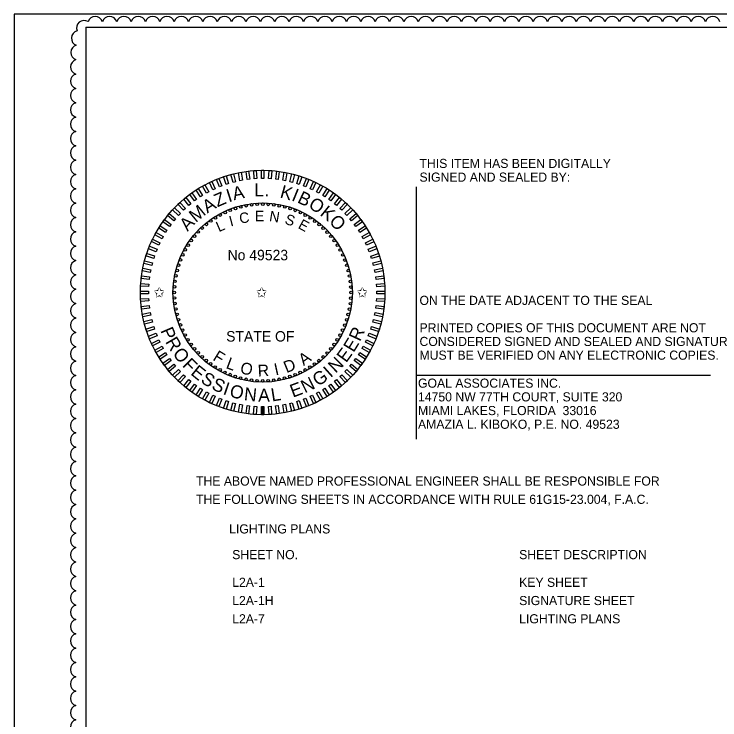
# Model space of a CAD drawing. Extents: x -811 to 10319, y -2309 to 9962.
# Drawn here: x -811.43 to -806.03, y -2291.82 to -2286.41 of the extents above; entities that cross this region are included whole.
import ezdxf

# ---------------------------------------------------------------- set-up
doc = ezdxf.new("R2010")
doc.units = 0
for name, color, linetype in [('AdhocPoint_dp', 7, 'Continuous'), ('PlotBorder_dp', 7, 'Continuous'), ('ScratchEle_dp', 7, 'Continuous'), ('TextMinor', 7, 'Continuous'), ('TextMisc', 7, 'Continuous'), ('TextNotes', 7, 'Continuous'), ('TextShtNo', 7, 'Continuous')]:
    doc.layers.add(name, color=color, linetype=linetype)

msp = doc.modelspace()

# ---------------------------------------------------------------- linework, layer by layer
at = {"layer": 'AdhocPoint_dp'}
for p, q in [((-808.3546, -2287.7325), (-808.3546, -2289.6672)), ((-808.3546, -2289.1772), (-806.0979, -2289.1772))]:
    msp.add_line(p, q, dxfattribs=at)
at = {"layer": 'PlotBorder_dp'}
msp.add_lwpolyline([(-811.435, -2297.0086), (-794.935, -2297.0086), (-794.935, -2286.4086), (-811.435, -2286.4086)], close=True, dxfattribs=at)
at = {"layer": 'ScratchEle_dp'}
for centre, start, end in [((-810.8137, -2286.4839), 17.5, 162.5), ((-810.7037, -2286.4839), 17.5, 162.5), ((-810.5936, -2286.4839), 17.5, 162.5), ((-810.4836, -2286.4839), 17.5, 162.5), ((-810.3736, -2286.4839), 17.5, 162.5), ((-810.2635, -2286.4839), 17.5, 162.5), ((-810.1535, -2286.4839), 17.5, 162.5), ((-810.0434, -2286.4839), 17.5, 162.5), ((-809.9334, -2286.4839), 17.5, 162.5), ((-809.8233, -2286.4839), 17.5, 162.5), ((-809.7133, -2286.4839), 17.5, 162.5), ((-809.6033, -2286.4839), 17.5, 162.5), ((-809.4932, -2286.4839), 17.5, 162.5), ((-809.3832, -2286.4839), 17.5, 162.5), ((-809.2731, -2286.4839), 17.5, 162.5), ((-809.1631, -2286.4839), 17.5, 162.5), ((-809.053, -2286.4839), 17.5, 162.5), ((-808.943, -2286.4839), 17.5, 162.5), ((-808.8329, -2286.4839), 17.5, 162.5), ((-808.7229, -2286.4839), 17.5, 162.5), ((-808.6129, -2286.4839), 17.5, 162.5), ((-808.5028, -2286.4839), 17.5, 162.5), ((-808.3928, -2286.4839), 17.5, 162.5), ((-808.2827, -2286.4839), 17.5, 162.5), ((-808.1727, -2286.4839), 17.5, 162.5), ((-808.0626, -2286.4839), 17.5, 162.5), ((-807.9526, -2286.4839), 17.5, 162.5), ((-807.8425, -2286.4839), 17.5, 162.5), ((-807.7325, -2286.4839), 17.5, 162.5), ((-807.6225, -2286.4839), 17.5, 162.5), ((-807.5124, -2286.4839), 17.5, 162.5), ((-807.4024, -2286.4839), 17.5, 162.5), ((-807.2923, -2286.4839), 17.5, 162.5), ((-807.1823, -2286.4839), 17.5, 162.5), ((-807.0722, -2286.4839), 17.5, 162.5), ((-806.9622, -2286.4839), 17.5, 162.5), ((-806.8522, -2286.4839), 17.5, 162.5), ((-806.7421, -2286.4839), 17.5, 162.5), ((-806.6321, -2286.4839), 17.5, 162.5), ((-806.522, -2286.4839), 17.5, 162.5), ((-806.412, -2286.4839), 17.5, 162.5), ((-806.3019, -2286.4839), 17.5, 162.5), ((-806.1919, -2286.4839), 17.5, 162.5), ((-806.0818, -2286.4839), 17.5, 162.5), ((-810.8994, -2286.5154), 57.9093, 202.9093), ((-810.9383, -2286.5938), 104.3048, 249.3048), ((-810.9427, -2286.7032), 106.1121, 251.1121), ((-810.9446, -2286.813), 106.8288, 251.8288), ((-810.9455, -2286.9229), 107.2443, 252.2443), ((-810.9458, -2287.0329), 107.4812, 252.4812), ((-810.9458, -2287.1429), 107.5, 252.5), ((-810.9458, -2287.253), 107.5, 252.5), ((-810.9458, -2287.363), 107.5, 252.5), ((-810.9458, -2287.4731), 107.5, 252.5), ((-810.9458, -2287.5831), 107.5, 252.5), ((-810.9458, -2287.6932), 107.5, 252.5), ((-810.9458, -2287.8032), 107.5, 252.5), ((-810.9458, -2287.9132), 107.5, 252.5), ((-810.9458, -2288.0233), 107.5, 252.5), ((-810.9458, -2288.1333), 107.5, 252.5), ((-810.9458, -2288.2434), 107.5, 252.5), ((-810.9458, -2288.3534), 107.5, 252.5), ((-810.9458, -2288.4635), 107.5, 252.5), ((-810.9458, -2288.5735), 107.5, 252.5), ((-810.9458, -2288.6835), 107.5, 252.5), ((-810.9458, -2288.7936), 107.5, 252.5), ((-810.9458, -2288.9036), 107.5, 252.5), ((-810.9458, -2289.0137), 107.5, 252.5), ((-810.9458, -2289.1237), 107.5, 252.5), ((-810.9458, -2289.2338), 107.5, 252.5), ((-810.9458, -2289.3438), 107.5, 252.5), ((-810.9458, -2289.4539), 107.5, 252.5), ((-810.9458, -2289.5639), 107.5, 252.5), ((-810.9458, -2289.6739), 107.5, 252.5), ((-810.9458, -2289.784), 107.5, 252.5), ((-810.9458, -2289.894), 107.5, 252.5), ((-810.9458, -2290.0041), 107.5, 252.5), ((-810.9458, -2290.1141), 107.5, 252.5), ((-810.9458, -2290.2242), 107.5, 252.5), ((-810.9458, -2290.3342), 107.5, 252.5), ((-810.9458, -2290.4442), 107.5, 252.5), ((-810.9458, -2290.5543), 107.5, 252.5), ((-810.9458, -2290.6643), 107.5, 252.5), ((-810.9458, -2290.7744), 107.5, 252.5), ((-810.9458, -2290.8844), 107.5, 252.5), ((-810.9458, -2290.9945), 107.5, 252.5), ((-810.9458, -2291.1045), 107.5, 252.5), ((-810.9458, -2291.2146), 107.5, 252.5), ((-810.9458, -2291.3246), 107.5, 252.5), ((-810.9458, -2291.4346), 107.5, 252.5), ((-810.9458, -2291.5447), 107.5, 252.5), ((-810.9458, -2291.6547), 107.5, 252.5), ((-810.9458, -2291.7648), 107.5001, 252.5001), ((-810.9458, -2291.8748), 107.5029, 252.5029)]:
    msp.add_arc(centre, 0.0577, start, end, dxfattribs=at)
at = {"layer": 'TextMinor'}
for radius in [0.9371, 0.6872]:
    msp.add_circle((-809.5304, -2288.5431), radius, dxfattribs=at)
at = {"layer": 'TextNotes'}
for q in [(-810.885, -2296.9086), (-795.485, -2286.5086)]:
    msp.add_line((-810.885, -2286.5086), q, dxfattribs=at)
at = {"layer": 'TextShtNo'}
for p, q in [((-809.5404, -2289.4802), (-809.5406, -2289.4178)), ((-809.5304, -2289.4802), (-809.5306, -2289.4177)), ((-809.5204, -2289.4802), (-809.5206, -2289.4177))]:
    msp.add_line(p, q, dxfattribs=at)
for points in [[(-809.6843, -2287.682), (-809.7041, -2287.6858), (-809.7158, -2287.6245), (-809.696, -2287.6207)], [(-809.6299, -2287.674), (-809.6499, -2287.6765), (-809.6578, -2287.6146), (-809.6377, -2287.6121)], [(-809.5752, -2287.6695), (-809.5953, -2287.6708), (-809.5992, -2287.6085), (-809.5791, -2287.6072)], [(-809.5202, -2287.6684), (-809.5404, -2287.6684), (-809.5404, -2287.606), (-809.5202, -2287.606)], [(-809.4653, -2287.6708), (-809.4855, -2287.6695), (-809.4815, -2287.6072), (-809.4614, -2287.6085)], [(-809.4107, -2287.6766), (-809.4307, -2287.674), (-809.4229, -2287.6121), (-809.4028, -2287.6146)], [(-809.3565, -2287.6858), (-809.3763, -2287.682), (-809.3646, -2287.6207), (-809.3448, -2287.6245)], [(-809.8429, -2287.7261), (-809.8617, -2287.7335), (-809.8847, -2287.6755), (-809.8659, -2287.668)], [(-809.791, -2287.7081), (-809.8102, -2287.7143), (-809.8295, -2287.6549), (-809.8103, -2287.6487)], [(-809.7381, -2287.6933), (-809.7576, -2287.6984), (-809.7731, -2287.6379), (-809.7536, -2287.6329)], [(-809.303, -2287.6984), (-809.3226, -2287.6934), (-809.307, -2287.6329), (-809.2875, -2287.638)], [(-809.2504, -2287.7144), (-809.2696, -2287.7081), (-809.2503, -2287.6488), (-809.2311, -2287.655)], [(-809.1989, -2287.7336), (-809.2177, -2287.7261), (-809.1947, -2287.6681), (-809.176, -2287.6755)], [(-809.9429, -2287.7717), (-809.9605, -2287.7814), (-809.9906, -2287.7267), (-809.9729, -2287.717)], [(-809.8936, -2287.7473), (-809.9119, -2287.7559), (-809.9384, -2287.6994), (-809.9202, -2287.6908)], [(-809.1488, -2287.756), (-809.167, -2287.7474), (-809.1404, -2287.6909), (-809.1222, -2287.6995)], [(-809.1001, -2287.7815), (-809.1178, -2287.7718), (-809.0877, -2287.7171), (-809.07, -2287.7268)], [(-810.0363, -2287.8295), (-810.0526, -2287.8413), (-810.0893, -2287.7908), (-810.073, -2287.779)], [(-809.9905, -2287.7991), (-810.0075, -2287.8099), (-810.041, -2287.7572), (-810.0239, -2287.7464)], [(-809.0531, -2287.81), (-809.0702, -2287.7992), (-809.0367, -2287.7465), (-809.0197, -2287.7573)], [(-809.008, -2287.8414), (-809.0244, -2287.8296), (-808.9877, -2287.7791), (-808.9713, -2287.7909)], [(-810.0801, -2287.8626), (-810.0956, -2287.8755), (-810.1354, -2287.8274), (-810.1199, -2287.8145)], [(-808.965, -2287.8756), (-808.9806, -2287.8628), (-808.9408, -2287.8147), (-808.9252, -2287.8275)], [(-810.1217, -2287.8985), (-810.1364, -2287.9123), (-810.1792, -2287.8668), (-810.1645, -2287.853)], [(-808.9242, -2287.9124), (-808.9389, -2287.8986), (-808.8962, -2287.8531), (-808.8815, -2287.8669)], [(-810.1979, -2287.9777), (-810.2107, -2287.9932), (-810.2588, -2287.9535), (-810.246, -2287.9379)], [(-810.161, -2287.9369), (-810.1749, -2287.9516), (-810.2204, -2287.9089), (-810.2065, -2287.8942)], [(-808.8858, -2287.9517), (-808.8996, -2287.937), (-808.8541, -2287.8943), (-808.8403, -2287.909)], [(-808.85, -2287.9934), (-808.8628, -2287.9778), (-808.8147, -2287.938), (-808.8019, -2287.9536)], [(-810.232, -2288.0207), (-810.2439, -2288.037), (-810.2944, -2288.0004), (-810.2825, -2287.984)], [(-808.8168, -2288.0372), (-808.8286, -2288.0209), (-808.7781, -2287.9842), (-808.7663, -2288.0005)], [(-810.2635, -2288.0658), (-810.2743, -2288.0828), (-810.327, -2288.0494), (-810.3162, -2288.0324)], [(-808.7864, -2288.083), (-808.7972, -2288.066), (-808.7445, -2288.0325), (-808.7337, -2288.0496)], [(-810.292, -2288.1128), (-810.3017, -2288.1305), (-810.3564, -2288.1004), (-810.3467, -2288.0827)], [(-808.759, -2288.1306), (-808.7687, -2288.1129), (-808.714, -2288.0829), (-808.7043, -2288.1006)], [(-810.3175, -2288.1614), (-810.3261, -2288.1797), (-810.3826, -2288.1531), (-810.374, -2288.1349)], [(-808.7346, -2288.1799), (-808.7432, -2288.1616), (-808.6867, -2288.135), (-808.6782, -2288.1533)], [(-810.3399, -2288.2116), (-810.3473, -2288.2304), (-810.4054, -2288.2074), (-810.3979, -2288.1886)], [(-808.7134, -2288.2306), (-808.7208, -2288.2118), (-808.6628, -2288.1888), (-808.6554, -2288.2076)], [(-810.3591, -2288.2631), (-810.3654, -2288.2823), (-810.4247, -2288.263), (-810.4185, -2288.2438)], [(-808.6954, -2288.2825), (-808.7016, -2288.2633), (-808.6423, -2288.244), (-808.636, -2288.2632)], [(-810.3751, -2288.3157), (-810.3801, -2288.3352), (-810.4405, -2288.3197), (-810.4355, -2288.3002)], [(-808.6807, -2288.3354), (-808.6857, -2288.3159), (-808.6252, -2288.3004), (-808.6202, -2288.3199)], [(-810.3877, -2288.3692), (-810.3915, -2288.389), (-810.4528, -2288.3773), (-810.449, -2288.3575)], [(-808.6693, -2288.3892), (-808.6731, -2288.3694), (-808.6118, -2288.3577), (-808.608, -2288.3775)], [(-810.3969, -2288.4234), (-810.3994, -2288.4434), (-810.4614, -2288.4355), (-810.4588, -2288.4155)], [(-808.6613, -2288.4436), (-808.6639, -2288.4235), (-808.6019, -2288.4157), (-808.5994, -2288.4357)], [(-810.4027, -2288.478), (-810.404, -2288.4981), (-810.4663, -2288.4942), (-810.465, -2288.4741)], [(-808.6568, -2288.4983), (-808.6581, -2288.4782), (-808.5958, -2288.4743), (-808.5945, -2288.4944)], [(-810.4051, -2288.5329), (-810.4051, -2288.5531), (-810.4675, -2288.5531), (-810.4675, -2288.5329)], [(-808.6557, -2288.5533), (-808.6557, -2288.5331), (-808.5933, -2288.5331), (-808.5933, -2288.5533)], [(-810.404, -2288.5878), (-810.4027, -2288.608), (-810.465, -2288.6119), (-810.4663, -2288.5918)], [(-808.6581, -2288.6082), (-808.6568, -2288.588), (-808.5945, -2288.5919), (-808.5958, -2288.6121)], [(-810.3995, -2288.6426), (-810.3969, -2288.6626), (-810.4589, -2288.6704), (-810.4614, -2288.6504)], [(-808.6639, -2288.6628), (-808.6614, -2288.6428), (-808.5994, -2288.6506), (-808.602, -2288.6706)], [(-810.3915, -2288.697), (-810.3877, -2288.7168), (-810.449, -2288.7285), (-810.4528, -2288.7087)], [(-808.6731, -2288.717), (-808.6693, -2288.6972), (-808.608, -2288.7089), (-808.6118, -2288.7287)], [(-810.3801, -2288.7507), (-810.3751, -2288.7703), (-810.4356, -2288.7858), (-810.4406, -2288.7663)], [(-808.6857, -2288.7705), (-808.6807, -2288.7509), (-808.6203, -2288.7664), (-808.6253, -2288.786)], [(-810.3654, -2288.8037), (-810.3592, -2288.8229), (-810.4185, -2288.8422), (-810.4248, -2288.823)], [(-808.7017, -2288.8231), (-808.6954, -2288.8039), (-808.6361, -2288.8232), (-808.6423, -2288.8423)], [(-810.3474, -2288.8556), (-810.34, -2288.8744), (-810.398, -2288.8973), (-810.4054, -2288.8786)], [(-808.7209, -2288.8745), (-808.7135, -2288.8558), (-808.6554, -2288.8788), (-808.6629, -2288.8975)], [(-810.3262, -2288.9063), (-810.3176, -2288.9245), (-810.3741, -2288.9511), (-810.3826, -2288.9329)], [(-808.7433, -2288.9247), (-808.7347, -2288.9065), (-808.6782, -2288.933), (-808.6868, -2288.9513)], [(-810.3018, -2288.9555), (-810.2921, -2288.9732), (-810.3468, -2289.0033), (-810.3565, -2288.9856)], [(-808.7688, -2288.9734), (-808.7591, -2288.9557), (-808.7044, -2288.9858), (-808.7141, -2289.0035)], [(-810.2744, -2289.0032), (-810.2636, -2289.0202), (-810.3163, -2289.0536), (-810.3271, -2289.0366)], [(-808.7973, -2289.0204), (-808.7865, -2289.0033), (-808.7338, -2289.0368), (-808.7446, -2289.0538)], [(-810.244, -2289.049), (-810.2322, -2289.0653), (-810.2826, -2289.102), (-810.2945, -2289.0857)], [(-808.8288, -2289.0654), (-808.8169, -2289.0491), (-808.7664, -2289.0858), (-808.7783, -2289.1021)], [(-810.2108, -2289.0928), (-810.198, -2289.1083), (-810.2461, -2289.1481), (-810.2589, -2289.1326)], [(-810.175, -2289.1344), (-810.1612, -2289.1491), (-810.2067, -2289.1919), (-810.2205, -2289.1771)], [(-808.8998, -2289.1493), (-808.8859, -2289.1346), (-808.8404, -2289.1773), (-808.8543, -2289.192)], [(-808.8629, -2289.1085), (-808.8501, -2289.0929), (-808.802, -2289.1327), (-808.8148, -2289.1483)], [(-810.1366, -2289.1737), (-810.1219, -2289.1875), (-810.1646, -2289.233), (-810.1793, -2289.2192)], [(-808.9391, -2289.1877), (-808.9244, -2289.1739), (-808.8816, -2289.2193), (-808.8963, -2289.2332)], [(-810.0958, -2289.2105), (-810.0802, -2289.2234), (-810.12, -2289.2715), (-810.1356, -2289.2586)], [(-810.0528, -2289.2447), (-810.0364, -2289.2566), (-810.0731, -2289.3071), (-810.0894, -2289.2952)], [(-809.0245, -2289.2567), (-809.0082, -2289.2448), (-808.9715, -2289.2953), (-808.9878, -2289.3072)], [(-808.9807, -2289.2235), (-808.9652, -2289.2107), (-808.9254, -2289.2588), (-808.9409, -2289.2716)], [(-810.0077, -2289.2761), (-809.9906, -2289.287), (-810.0241, -2289.3397), (-810.0411, -2289.3288)], [(-809.0703, -2289.2871), (-809.0533, -2289.2762), (-809.0198, -2289.3289), (-809.0369, -2289.3398)], [(-809.9607, -2289.3047), (-809.943, -2289.3144), (-809.9731, -2289.3691), (-809.9908, -2289.3594)], [(-809.912, -2289.3302), (-809.8938, -2289.3388), (-809.9203, -2289.3952), (-809.9386, -2289.3867)], [(-809.8619, -2289.3526), (-809.8431, -2289.36), (-809.8661, -2289.418), (-809.8848, -2289.4106)], [(-809.2179, -2289.3601), (-809.1991, -2289.3527), (-809.1761, -2289.4107), (-809.1949, -2289.4181)], [(-809.1672, -2289.3388), (-809.1489, -2289.3303), (-809.1224, -2289.3867), (-809.1406, -2289.3953)], [(-809.1179, -2289.3145), (-809.1003, -2289.3048), (-809.0702, -2289.3594), (-809.0879, -2289.3692)], [(-809.8104, -2289.3718), (-809.7912, -2289.378), (-809.8105, -2289.4374), (-809.8297, -2289.4312)], [(-809.7578, -2289.3877), (-809.7382, -2289.3928), (-809.7538, -2289.4532), (-809.7733, -2289.4482)], [(-809.7043, -2289.4004), (-809.6845, -2289.4041), (-809.6962, -2289.4654), (-809.716, -2289.4617)], [(-809.3765, -2289.4042), (-809.3567, -2289.4004), (-809.345, -2289.4617), (-809.3648, -2289.4655)], [(-809.3227, -2289.3928), (-809.3032, -2289.3878), (-809.2877, -2289.4482), (-809.3072, -2289.4533)], [(-809.2698, -2289.3781), (-809.2506, -2289.3719), (-809.2313, -2289.4312), (-809.2505, -2289.4375)], [(-809.6501, -2289.4096), (-809.6301, -2289.4121), (-809.6379, -2289.474), (-809.6579, -2289.4715)], [(-809.5955, -2289.4154), (-809.5753, -2289.4167), (-809.5793, -2289.479), (-809.5994, -2289.4777)], [(-809.5406, -2289.4178), (-809.5204, -2289.4178), (-809.5204, -2289.4802), (-809.5406, -2289.4802)], [(-809.4856, -2289.4167), (-809.4655, -2289.4154), (-809.4616, -2289.4777), (-809.4817, -2289.479)], [(-809.4309, -2289.4121), (-809.4109, -2289.4096), (-809.403, -2289.4715), (-809.4231, -2289.4741)]]:
    msp.add_lwpolyline(points, close=True, dxfattribs=at)
for centre in [(-809.7391, -2287.8989), (-809.6983, -2287.887), (-809.6567, -2287.8778), (-809.6147, -2287.8712), (-809.5724, -2287.8672), (-809.5298, -2287.8659), (-809.4873, -2287.8673), (-809.445, -2287.8713), (-809.403, -2287.878), (-809.3614, -2287.8873), (-809.3206, -2287.8992), (-809.8561, -2287.9494), (-809.8182, -2287.9301), (-809.7792, -2287.9132), (-809.2806, -2287.9136), (-809.2416, -2287.9306), (-809.2037, -2287.9499), (-809.928, -2287.9949), (-809.8928, -2287.971), (-809.1671, -2287.9716), (-809.1319, -2287.9955), (-809.9936, -2288.049), (-809.9616, -2288.0209), (-809.0983, -2288.0216), (-809.0664, -2288.0498), (-810.0518, -2288.111), (-810.0237, -2288.0791), (-809.0364, -2288.0799), (-809.0082, -2288.1119), (-810.0779, -2288.1446), (-808.9822, -2288.1455), (-810.1236, -2288.2163), (-810.1019, -2288.1797), (-808.9583, -2288.1807), (-808.9367, -2288.2173), (-810.1429, -2288.2542), (-808.9174, -2288.2553), (-810.1743, -2288.3333), (-810.1598, -2288.2933), (-808.9005, -2288.2943), (-808.8862, -2288.3343), (-810.1862, -2288.3741), (-808.8743, -2288.3752), (-810.1955, -2288.4156), (-808.8651, -2288.4167), (-810.2022, -2288.4576), (-808.8585, -2288.4588), (-810.2076, -2288.5425), (-810.2062, -2288.5), (-808.8545, -2288.5011), (-808.8532, -2288.5436), (-810.2063, -2288.585), (-808.8546, -2288.5862), (-810.2023, -2288.6274), (-808.8586, -2288.6285), (-810.1957, -2288.6694), (-810.1865, -2288.7109), (-808.8746, -2288.712), (-808.8653, -2288.6705), (-810.1746, -2288.7518), (-808.8865, -2288.7529), (-810.1602, -2288.7918), (-808.901, -2288.7929), (-810.1434, -2288.8309), (-810.1241, -2288.8688), (-808.9372, -2288.8698), (-808.9179, -2288.8319), (-810.1025, -2288.9055), (-808.9589, -2288.9064), (-810.0786, -2288.9407), (-810.0525, -2288.9743), (-809.009, -2288.9752), (-808.9829, -2288.9416), (-810.0244, -2289.0062), (-809.9944, -2289.0363), (-809.0672, -2289.0371), (-809.0371, -2289.0071), (-809.9625, -2289.0645), (-809.9289, -2289.0906), (-809.1328, -2289.0913), (-809.0992, -2289.0652), (-809.8937, -2289.1146), (-809.8571, -2289.1362), (-809.2046, -2289.1368), (-809.168, -2289.1152), (-809.8192, -2289.1556), (-809.7802, -2289.1725), (-809.7402, -2289.187), (-809.6994, -2289.1989), (-809.3625, -2289.1991), (-809.3217, -2289.1873), (-809.2816, -2289.1729), (-809.2426, -2289.1561), (-809.6578, -2289.2082), (-809.6158, -2289.2149), (-809.5735, -2289.2189), (-809.5304, -2289.2203), (-809.4884, -2289.219), (-809.4461, -2289.215), (-809.4041, -2289.2084)]:
    msp.add_circle(centre, 0.01, dxfattribs=at)

# ---------------------------------------------------------------- texts
at = {"layer": 'PlotBorder_dp'}
for s, height, p in [('THIS ITEM HAS BEEN DIGITALLY', 0.07, (-808.3286, -2287.5884)), ('SIGNED AND SEALED BY:', 0.07, (-808.3286, -2287.6934)), ('No 49523', 0.07997, (-809.7993, -2288.2959)), ('ON THE DATE ADJACENT TO THE SEAL', 0.07, (-808.3286, -2288.6384)), ('PRINTED COPIES OF THIS DOCUMENT ARE NOT ', 0.07, (-808.3286, -2288.8484)), ('STATE OF', 0.07997, (-809.81, -2288.9191)), ('CONSIDERED SIGNED AND SEALED AND SIGNATURE ', 0.07, (-808.3286, -2288.9534)), ('MUST BE VERIFIED ON ANY ELECTRONIC COPIES.', 0.07, (-808.3286, -2289.0584)), ('GOAL ASSOCIATES INC.', 0.07, (-808.3401, -2289.2731)), ('14750 NW 77TH COURT, SUITE 320', 0.07, (-808.3401, -2289.3781)), ('MIAMI LAKES, FLORIDA  33016', 0.07, (-808.3401, -2289.4831)), ('AMAZIA L. KIBOKO, P.E. NO. 49523', 0.07, (-808.3401, -2289.5881)), ('THE ABOVE NAMED PROFESSIONAL ENGINEER SHALL BE RESPONSIBLE FOR ', 0.07, (-810.041, -2290.0235)), ('THE FOLLOWING SHEETS IN ACCORDANCE WITH RULE 61G15-23.004, F.A.C.', 0.07, (-810.041, -2290.1635)), ('LIGHTING PLANS', 0.07, (-809.7873, -2290.3906))]:
    msp.add_text(s, height=height, dxfattribs=at).set_placement(p)
for s, height, rotation, p in [('A', 0.1, 11.9184, (-809.7511, -2287.8364)), ('L', 0.1, 359.9662, (-809.594, -2287.8061)), ('K', 0.1, 344.2727, (-809.4034, -2287.8133)), ('Z', 0.1, 23.3052, (-809.8772, -2287.89)), ('I', 0.1, 17.6836, (-809.7904, -2287.8524)), ('I', 0.1, 337.7777, (-809.3148, -2287.8351)), ('B', 0.1, 334.487, (-809.2709, -2287.8504)), ('A', 0.1, 31.466, (-809.9546, -2287.9386)), ('.', 0.1, 353.7858, (-809.5173, -2287.8032)), ('O', 0.1, 327.8239, (-809.1862, -2287.889)), ('M', 0.1, 39.3, (-810.0436, -2288.0107)), ('K', 0.1, 321.0594, (-809.0967, -2287.9461)), ('A', 0.1, 46.8094, (-810.1058, -2288.0792)), ('O', 0.1, 314.2033, (-809.027, -2288.0037)), ('P', 0.1, 293.1955, (-810.3158, -2288.8345)), ('R', 0.1, 65.2886, (-808.7843, -2288.9239)), ('R', 0.1, 300.2595, (-810.2789, -2288.9204)), ('E', 0.1, 58.6169, (-808.8335, -2289.0078)), ('O', 0.1, 307.2662, (-810.2248, -2289.0122)), ('E', 0.1, 53.9986, (-808.8907, -2289.0865)), ('F', 0.09, 328.534, (-809.9187, -2289.0582)), ('A', 0.09, 35.5463, (-809.2161, -2289.1075)), ('F', 0.1, 314.2033, (-810.1514, -2289.1047)), ('L', 0.09, 339.4875, (-809.8175, -2289.1211)), ('O', 0.09, 348.0816, (-809.7081, -2289.1617)), ('D', 0.09, 22.2223, (-809.3478, -2289.1619)), ('N', 0.1, 44.3421, (-808.9707, -2289.1663)), ('E', 0.1, 321.0594, (-810.0881, -2289.1682)), ('R', 0.09, 3.1074, (-809.566, -2289.1879)), ('I', 0.09, 12.5248, (-809.4319, -2289.1788)), ('I', 0.1, 41.8391, (-809.0101, -2289.2005)), ('S', 0.1, 327.8239, (-810.0119, -2289.2287)), ('N', 0.1, 26.0618, (-809.2073, -2289.3167)), ('G', 0.1, 34.1136, (-809.1062, -2289.2665)), ('S', 0.1, 334.487, (-809.9288, -2289.2801)), ('I', 0.1, 341.04, (-809.8403, -2289.3214)), ('E', 0.1, 20.5125, (-809.2988, -2289.3499)), ('O', 0.1, 344.2727, (-809.7911, -2289.339)), ('N', 0.1, 353.7858, (-809.6768, -2289.3689)), ('A', 0.1, 359.9662, (-809.5645, -2289.3799)), ('L', 0.1, 8.9826, (-809.459, -2289.379))]:
    msp.add_text(s, height=height, rotation=rotation, dxfattribs=at).set_placement(p)
at = {"layer": 'TextMisc'}
for s, p in [('SHEET NO.', (-809.7639, -2290.5876)), ('SHEET DESCRIPTION', (-807.5649, -2290.5876)), ('L2A-1', (-809.7639, -2290.7997)), ('KEY SHEET', (-807.5649, -2290.7997)), ('L2A-1H', (-809.7639, -2290.9397)), ('SIGNATURE SHEET', (-807.5649, -2290.9397)), ('L2A-7', (-809.7639, -2291.0797)), ('LIGHTING PLANS', (-807.5649, -2291.0797))]:
    msp.add_text(s, height=0.07, dxfattribs=at).set_placement(p)
at = {"layer": 'TextShtNo'}
for s, rotation, p in [('C', 8.9826, (-809.7033, -2288.0154)), ('E', 359.9662, (-809.5906, -2287.9965)), ('N', 350.6464, (-809.4838, -2287.9951)), ('S', 341.04, (-809.3667, -2288.0139)), ('L', 23.3052, (-809.8664, -2288.0809)), ('I', 14.8189, (-809.7758, -2288.0381)), ('E', 331.1686, (-809.2653, -2288.0464))]:
    msp.add_text(s, height=0.08, rotation=rotation, dxfattribs=at).set_placement(p)
for p in [(-810.365, -2288.581), (-809.5806, -2288.581), (-808.8091, -2288.581)]:
    msp.add_text('✩', height=0.08, dxfattribs=at).set_placement(p)

doc.saveas('drawing.dxf')
